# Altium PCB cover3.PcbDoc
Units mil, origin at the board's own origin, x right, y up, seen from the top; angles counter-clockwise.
Board outline 7500 x 2300 mil, 2 copper layers (Top Layer, Bottom Layer); 34 components, 23 nets, 169 pads, 36 vias.
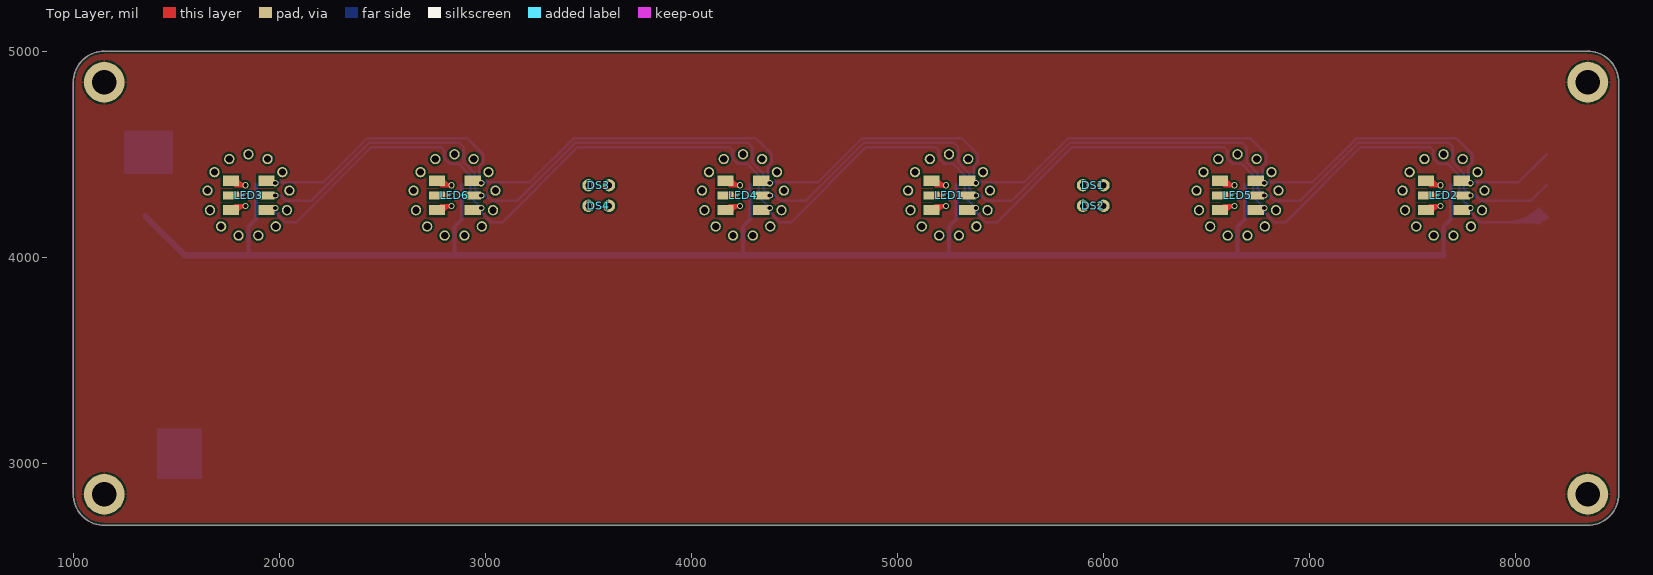
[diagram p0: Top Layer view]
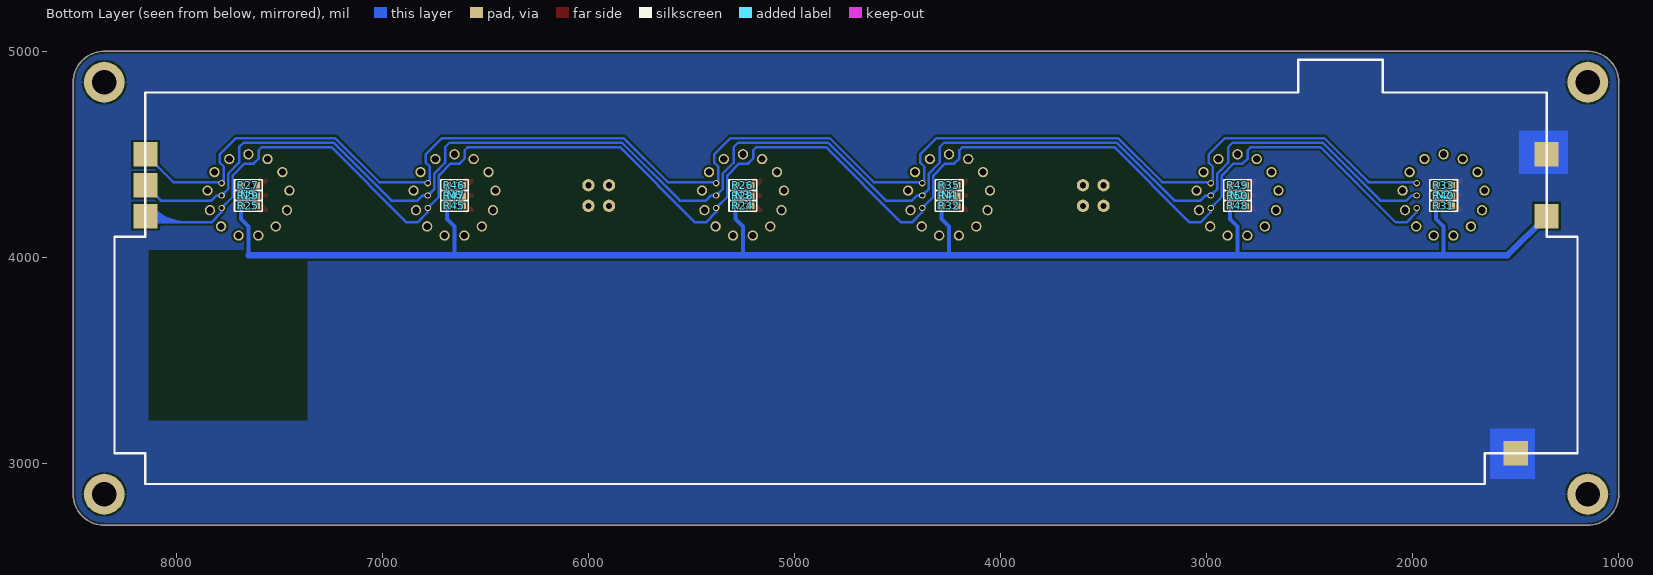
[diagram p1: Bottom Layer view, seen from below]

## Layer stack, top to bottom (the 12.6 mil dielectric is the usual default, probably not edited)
Top Solder: solder mask 0.4, Solder Resist, Dk 3.5
Top Layer: signal copper 1.4
Dielectric 1: dielectric 12.6, FR-4, Dk 4.8
Bottom Layer: signal copper 1.4
Bottom Solder: solder mask 0.4, Solder Resist, Dk 3.5

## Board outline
1150,2700 cw(c1150,2850) 1000,2850 1000,4850 cw(c1150,4850) 1150,5000 8350,5000 cw(c8350,4850) 8500,4850 8500,2850 cw(c8350,2850) 8350,2700

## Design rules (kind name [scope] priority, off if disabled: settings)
Clearance [All] p1: gap=10
PolygonConnect [All] p1: connectstyle=Relief reliefconductorwidth=10 reliefentries=4 polygonreliefangle="90 Angle" airgapwidth=10
RoutingVias [All] p1: holewidth=28 width=50 viastyle="Through Hole" minholewidth=28 minwidth=50 maxholewidth=28 maxwidth=50
SolderMaskExpansion [All] p1: expansion=4
Width [All] p1: maxlimit=10 minlimit=10 preferedwidth=10
29 further rules are at their usual default settings.

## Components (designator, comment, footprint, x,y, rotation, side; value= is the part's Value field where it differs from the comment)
DS1 "Lamp Neon" LED_PIN2 5900,4350 r0 top
DS2 "Lamp Neon" LED_PIN2 5900,4250 r0 top
DS3 "Lamp Neon" LED_PIN2 3600,4350 r180 top
DS4 "Lamp Neon" LED_PIN2 3600,4250 r180 top
LED1 "LED_RGB_5050" LED_RGB_5050 5165,4230 r90 top
LED2 "LED_RGB_5050" LED_RGB_5050 7565,4230 r90 top
LED3 "LED_RGB_5050" LED_RGB_5050 1765,4230 r90 top
LED4 "LED_RGB_5050" LED_RGB_5050 4165,4230 r90 top
LED5 "LED_RGB_5050" LED_RGB_5050 6565,4230 r90 top
LED6 "LED_RGB_5050" LED_RGB_5050 2765,4230 r90 top
N1 "ИН-14" IN14 2850,4300 r0 bottom
N2 "ИН-14" IN14 1850,4300 r0 bottom
N3 "ИН-14" IN14 5250,4300 r0 bottom
N4 "ИН-14" IN14 4250,4300 r0 bottom
N5 "ИН-14" IN14 7650,4300 r0 bottom
N6 "ИН-14" IN14 6650,4300 r0 bottom
R24 "Res2" "R 0603" 5250,4250 r0 bottom
R25 "Res2" "R 0603" 7650,4250 r0 bottom
R26 "Res2" "R 0603" 5250,4350 r0 bottom
R27 "Res2" "R 0603" 7650,4350 r0 bottom
R28 "Res2" "R 0603" 5250,4300 r0 bottom
R29 "Res2" "R 0603" 7650,4300 r0 bottom
R31 "Res2" "R 0603" 1850,4250 r0 bottom
R32 "Res2" "R 0603" 4250,4250 r0 bottom
R33 "Res2" "R 0603" 1850,4350 r0 bottom
R35 "Res2" "R 0603" 4250,4350 r0 bottom
R40 "Res2" "R 0603" 1850,4300 r0 bottom
R41 "Res2" "R 0603" 4250,4300 r0 bottom
R45 "Res2" "R 0603" 6650,4250 r0 bottom
R46 "Res2" "R 0603" 6650,4350 r0 bottom
R47 "Res2" "R 0603" 6650,4300 r0 bottom
R48 "Res2" "R 0603" 2850,4250 r0 bottom
R49 "Res2" "R 0603" 2850,4350 r0 bottom
R50 "Res2" "R 0603" 2850,4300 r0 bottom

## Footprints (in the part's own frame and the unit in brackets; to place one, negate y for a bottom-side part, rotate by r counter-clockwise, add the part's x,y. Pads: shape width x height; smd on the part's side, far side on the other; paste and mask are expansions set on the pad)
IN14 [mil]
  round 50 hole 35: 1(0,-200) 2(-93.03,-177.05) 3(-164.65,-113.54) 4(-198.55,-24.03) 5(-186.98,70.99) 6(-132.58,149.74) 7(-47.81,194.2) 8(47.91,194.18) 9(132.65,149.68) 10(187.01,70.89) 11(198.54,-24.13) 12(164.59,-113.63) 13(92.94,-177.09)
LED_PIN2 [mil] "Photosensitive Diode; 2 Leads"
  round 60 hole 30: 1(0,0) 2(100,0)
LED_RGB_5050 [mm]
  rect 1.27x2 smd: 0(0,0) 1(3.6,0) 3(0,-4.4) 4(3.6,-4.4)
  rect 1x2 smd: 2(1.778,0) 5(1.778,-4.4)
"R 0603" [mil] "1/10W贴片电阻"
  rect 40x31.5 smd: 1(-36.5,0) 2(36.5,0)
  silkscreen extent -68,-26 68,26, body extent -31,-16 31,16, height 16

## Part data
DS1 DS2 DS3 DS4: "Neon Lamp"
R24 R25 R26 R27 R28 R29 R31 R32 R33 R35 R40 R41 R45 R46 R47 R48 R49 R50: "Resistor"

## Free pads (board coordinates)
  round 196.85 hole 118.11: 0(1150,2850) 0(1150,4850) 0(8350,2850) 0(8350,4850)
  rect 118.11x118.11 smd far side: 0(8150,4500) 1(8150,4350) 2(8150,4200) 3(1350,4500) 4(1350,4200) 5(1500,3050)
  rect 118.11x118.11 on Bottom Solder: 5(1500,3050)

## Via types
v1: diameter 30, hole 20, Top Layer to Bottom Layer, 36 vias

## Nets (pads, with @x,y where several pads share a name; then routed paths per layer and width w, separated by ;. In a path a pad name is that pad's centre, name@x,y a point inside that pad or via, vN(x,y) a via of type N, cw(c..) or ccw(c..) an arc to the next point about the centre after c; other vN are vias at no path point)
5V: pad.4 R24.2 R25.2 R26.2 R27.2 R28.2 R29.2 R31.2 R32.2 R33.2 R35.2 R40.2 R41.2 R45.2 R46.2 R47.2 R48.2 R49.2 R50.2 | length 8509.4
  Bottom Layer w20: 1850,4010 1850,4150 1886.5,4186.5 R31.2 R40.2 R33.2 ; 2850,4010 2850,4150 2886.5,4186.5 R48.2 R50.2 R49.2 ; 4250,4010 4250,4150 4286.5,4186.5 R32.2 R41.2 R35.2 ; 5250,4010 5250,4150 5286.5,4186.5 R24.2 R28.2 R26.2 ; 6650,4010 6650,4150 6686.5,4186.5 R45.2 R47.2 R46.2 ; 7650,4010 7650,4150 7686.5,4186.5 R25.2 R29.2 R27.2
  Bottom Layer w30: pad.4 1540,4010 7650,4010
GND: pad.0@1150,2850 pad.0@1150,4850 pad.0@8350,2850 pad.0@8350,4850 pad.3 pad.5@1500,3050
LED_B: LED1.3 LED2.3 LED3.3 LED4.3 LED5.3 LED6.3 pad.2 | length 10835.3
  Bottom Layer w12: v1(1980,4240) 1980,4220 ; v1@2971,4240.07 ccw(c2949.85,4240.24) 2964.63,4255.37 ; v1@2971,4240.1 ccw(c2950.14,4240.35) 2965.06,4254.93 ccw(c2979.65,4269.86) v1@2979.9,4249 ; v1@2979.93,4249 cw(c2979.76,4270.15) 2964.63,4255.37 ; v1@4371,4240.07 ccw(c4349.85,4240.24) 4364.63,4255.37 ; v1@4371,4240.1 ccw(c4350.14,4240.35) 4365.06,4254.93 ccw(c4379.65,4269.86) v1@4379.9,4249 ; v1@4379.93,4249 cw(c4379.76,4270.15) 4364.63,4255.37 ; v1@5371,4240.07 ccw(c5349.85,4240.24) 5364.63,4255.37 ; v1@5371,4240.1 ccw(c5350.14,4240.35) 5365.06,4254.93 ccw(c5379.65,4269.86) v1@5379.9,4249 ; v1@5379.93,4249 cw(c5379.76,4270.15) 5364.63,4255.37 ; v1@6771,4240.07 ccw(c6749.85,4240.24) 6764.63,4255.37 ; v1@6771,4240.1 ccw(c6750.14,4240.35) 6765.06,4254.93 ccw(c6779.65,4269.86) v1@6779.9,4249 ; v1@6779.93,4249 cw(c6779.76,4270.15) 6764.63,4255.37 ; v1@7771,4240.07 ccw(c7749.85,4240.24) 7764.63,4255.37 ; v1@7771,4240.1 ccw(c7750.14,4240.35) 7765.06,4254.93 ccw(c7779.65,4269.86) v1@7779.9,4249 ; v1@7779.93,4249 cw(c7779.76,4270.15) 7764.63,4255.37 ; 8081.81,4179.65 ccw(c8066.43,4206.28) pad.2@8097.09,4203.98 ; 8083.99,4193.36 ccw(c8067.63,4220.72) pad.2@8098.55,4212.94 ; pad.2 8120,4170 7830,4170 7780,4220 ; 1980,4220 ccw(c1962.28,4220) 1974.03,4233.26 cw(c1962.28,4220) 1980,4220 ; 1980,4220 cw(c1997.72,4220) 1985.97,4233.26 ccw(c1997.72,4220) 1980,4220 ; 1980,4220 2030,4170 2082.23,4170 2447.23,4535 2785,4535 2800,4520 2800,4480 2825,4455 2868.89,4455 2926,4397.89 2926,4294 v1(2980,4240) 2980,4220 ; 2964.64,4255.36 ccw(c2980,4270.73) 2980,4249 cw(c2980,4270.73) 2964.64,4255.36 ; 2964.64,4255.36 cw(c2949.27,4240) 2971,4240 ccw(c2949.27,4240) 2964.64,4255.36 ; 2980,4220 ccw(c2962.28,4220) 2974.03,4233.26 cw(c2962.28,4220) 2980,4220 ; 2980,4220 cw(c2997.72,4220) 2985.97,4233.26 ccw(c2997.72,4220) 2980,4220 ; 2980,4220 3030,4170 3082.23,4170 3447.23,4535 4185,4535 4200,4520 4200,4480 4225,4455 4268.89,4455 4326,4397.89 4326,4294 v1(4380,4240) 4380,4220 ; 4364.64,4255.36 ccw(c4380,4270.73) 4380,4249 cw(c4380,4270.73) 4364.64,4255.36 ; 4364.64,4255.36 cw(c4349.27,4240) 4371,4240 ccw(c4349.27,4240) 4364.64,4255.36 ; 4380,4220 ccw(c4362.28,4220) 4374.03,4233.26 cw(c4362.28,4220) 4380,4220 ; 4380,4220 cw(c4397.72,4220) 4385.97,4233.26 ccw(c4397.72,4220) 4380,4220 ; 4380,4220 4430,4170 4482.23,4170 4847.23,4535 5185,4535 5200,4520 5200,4480 5225,4455 5268.89,4455 5326,4397.89 5326,4294 v1(5380,4240) 5380,4220 ; 5364.64,4255.36 ccw(c5380,4270.73) 5380,4249 cw(c5380,4270.73) 5364.64,4255.36 ; 5364.64,4255.36 cw(c5349.27,4240) 5371,4240 ccw(c5349.27,4240) 5364.64,4255.36 ; 5380,4220 ccw(c5362.28,4220) 5374.03,4233.26 cw(c5362.28,4220) 5380,4220 ; 5380,4220 cw(c5397.72,4220) 5385.97,4233.26 ccw(c5397.72,4220) 5380,4220 ; 5380,4220 5430,4170 5482.23,4170 5847.23,4535 6585,4535 6600,4520 6600,4480 6625,4455 6668.89,4455 6726,4397.89 6726,4294 v1(6780,4240) 6780,4220 ; 6764.64,4255.36 ccw(c6780,4270.73) 6780,4249 cw(c6780,4270.73) 6764.64,4255.36 ; 6764.64,4255.36 cw(c6749.27,4240) 6771,4240 ccw(c6749.27,4240) 6764.64,4255.36 ; 6780,4220 ccw(c6762.28,4220) 6774.03,4233.26 cw(c6762.28,4220) 6780,4220 ; 6780,4220 cw(c6797.72,4220) 6785.97,4233.26 ccw(c6797.72,4220) 6780,4220 ; 6780,4220 6830,4170 6882.23,4170 7247.23,4535 7585,4535 7600,4520 7600,4480 7625,4455 7668.89,4455 7726,4397.89 7726,4294 v1(7780,4240) 7780,4220 ; 7764.64,4255.36 ccw(c7780,4270.73) 7780,4249 cw(c7780,4270.73) 7764.64,4255.36 ; 7764.64,4255.36 cw(c7749.27,4240) 7771,4240 ccw(c7749.27,4240) 7764.64,4255.36 ; 7780,4220 ccw(c7762.28,4220) 7774.03,4233.26 cw(c7762.28,4220) 7780,4220 ; 7780,4220 cw(c7797.72,4220) 7785.97,4233.26 ccw(c7797.72,4220) 7780,4220 ; pad.2@8094.34,4170 ccw(c8094.34,4255.66) 8154.91,4195.09 cw(c8094.34,4255.66) pad.2@8094.34,4170 ; pad.2@8094.34,4170 cw(c8094.34,4144.34) 8112.48,4162.48 ccw(c8094.34,4144.34) pad.2@8094.34,4170 ; 7949.49,4170 ccw(c7949.49,4400.51) 8112.48,4237.52 cw(c7949.49,4400.51) 7949.49,4170 ; 7978.46,4170 ccw(c7978.46,4371.54) 8120.97,4229.03 cw(c7978.46,4371.54) 7978.46,4170 ; 8007.43,4170 ccw(c8007.43,4342.57) 8129.45,4220.55 cw(c8007.43,4342.57) 8007.43,4170 ; 8036.4,4170 ccw(c8036.4,4313.6) 8137.94,4212.06 cw(c8036.4,4313.6) 8036.4,4170 ; 8065.37,4170 ccw(c8065.37,4284.63) 8146.43,4203.57 cw(c8065.37,4284.63) 8065.37,4170
LED_G: LED1.4 LED2.4 LED3.4 LED4.4 LED5.4 LED6.4 pad.0@8150,4500 | length 7635.5
  Bottom Layer w12: v1@1985.13,4365.13 2215.13,4365.13 2429,4579 2911,4579 2990,4500 2990,4460 2970,4440 2970,4370 v1(2980,4360) 2985.13,4365.13 3215.13,4365.13 3429,4579 4311,4579 4390,4500 4390,4460 4370,4440 4370,4370 v1(4380,4360) ; v1@4385.13,4365.13 4615.13,4365.13 4829,4579 5311,4579 5390,4500 5390,4460 5370,4440 5370,4370 v1(5380,4360) 5385.13,4365.13 5615.13,4365.13 5829,4579 6711,4579 6790,4500 6790,4460 6770,4440 6770,4370 v1(6780,4360) ; v1@6785.13,4365.13 7015.13,4365.13 7229,4579 7711,4579 7790,4500 7790,4460 7770,4440 7770,4370 v1(7780,4360) 7785.13,4365.13 8015.13,4365.13 pad.0@8150,4500
  other v1: 1980,4360
LED_R: LED1.5 LED2.5 LED3.5 LED4.5 LED5.5 LED6.5 pad.1 | length 8903.8
  Bottom Layer w12: v1(1980,4300) 2005,4300 2030,4275 2156.11,4275 2438.11,4557 2873,4557 2895,4535 2895,4460 2948,4407 2948,4332 v1(2980,4300) 3005,4300 3030,4275 3156.11,4275 3438.11,4557 4273,4557 4295,4535 4295,4460 4348,4407 4348,4332 v1(4380,4300) 4405,4300 4430,4275 4556.11,4275 4838.11,4557 5273,4557 5295,4535 5295,4460 5348,4407 5348,4332 v1(5380,4300) 5405,4300 5430,4275 5556.11,4275 5838.11,4557 6673,4557 6695,4535 6695,4460 6748,4407 6748,4332 v1(6780,4300) 6805,4300 6830,4275 6956.11,4275 7238.11,4557 7673,4557 7695,4535 7695,4460 7748,4407 7748,4332 v1(7780,4300) 7805,4300 7830,4275 8075,4275 pad.1 ; v1@2971,4300.07 ccw(c2949.85,4300.24) 2964.63,4315.37 ; v1@2971,4300.1 ccw(c2950.14,4300.35) 2965.06,4314.93 ccw(c2979.65,4329.86) v1@2979.9,4309 ; v1@2979.93,4309 cw(c2979.76,4330.15) 2964.63,4315.37 ; v1@4371,4300.07 ccw(c4349.85,4300.24) 4364.63,4315.37 ; v1@4371,4300.1 ccw(c4350.14,4300.35) 4365.06,4314.93 ccw(c4379.65,4329.86) v1@4379.9,4309 ; v1@4379.93,4309 cw(c4379.76,4330.15) 4364.63,4315.37 ; v1@5371,4300.07 ccw(c5349.85,4300.24) 5364.63,4315.37 ; v1@5371,4300.1 ccw(c5350.14,4300.35) 5365.06,4314.93 ccw(c5379.65,4329.86) v1@5379.9,4309 ; v1@5379.93,4309 cw(c5379.76,4330.15) 5364.63,4315.37 ; v1@6771,4300.07 ccw(c6749.85,4300.24) 6764.63,4315.37 ; v1@6771,4300.1 ccw(c6750.14,4300.35) 6765.06,4314.93 ccw(c6779.65,4329.86) v1@6779.9,4309 ; v1@6779.93,4309 cw(c6779.76,4330.15) 6764.63,4315.37 ; v1@7771,4300.07 ccw(c7749.85,4300.24) 7764.63,4315.37 ; v1@7771,4300.1 ccw(c7750.14,4300.35) 7765.06,4314.93 ccw(c7779.65,4329.86) v1@7779.9,4309 ; v1@7779.93,4309 cw(c7779.76,4330.15) 7764.63,4315.37 ; 2001.73,4300 ccw(c2001.73,4278.27) 1986.36,4293.64 cw(c2001.73,4278.27) 2001.73,4300 ; 2001.73,4300 cw(c2001.73,4321.73) 1986.36,4306.36 ccw(c2001.73,4321.73) 2001.73,4300 ; 2964.64,4315.36 ccw(c2980,4330.73) 2980,4309 cw(c2980,4330.73) 2964.64,4315.36 ; 2964.64,4315.36 cw(c2949.27,4300) 2971,4300 ccw(c2949.27,4300) 2964.64,4315.36 ; 3001.73,4300 ccw(c3001.73,4278.27) 2986.36,4293.64 cw(c3001.73,4278.27) 3001.73,4300 ; 3001.73,4300 cw(c3001.73,4321.73) 2986.36,4306.36 ccw(c3001.73,4321.73) 3001.73,4300 ; 4364.64,4315.36 ccw(c4380,4330.73) 4380,4309 cw(c4380,4330.73) 4364.64,4315.36 ; 4364.64,4315.36 cw(c4349.27,4300) 4371,4300 ccw(c4349.27,4300) 4364.64,4315.36 ; 4401.73,4300 ccw(c4401.73,4278.27) 4386.36,4293.64 cw(c4401.73,4278.27) 4401.73,4300 ; 4401.73,4300 cw(c4401.73,4321.73) 4386.36,4306.36 ccw(c4401.73,4321.73) 4401.73,4300 ; 5364.64,4315.36 ccw(c5380,4330.73) 5380,4309 cw(c5380,4330.73) 5364.64,4315.36 ; 5364.64,4315.36 cw(c5349.27,4300) 5371,4300 ccw(c5349.27,4300) 5364.64,4315.36 ; 5401.73,4300 ccw(c5401.73,4278.27) 5386.36,4293.64 cw(c5401.73,4278.27) 5401.73,4300 ; 5401.73,4300 cw(c5401.73,4321.73) 5386.36,4306.36 ccw(c5401.73,4321.73) 5401.73,4300 ; 6764.64,4315.36 ccw(c6780,4330.73) 6780,4309 cw(c6780,4330.73) 6764.64,4315.36 ; 6764.64,4315.36 cw(c6749.27,4300) 6771,4300 ccw(c6749.27,4300) 6764.64,4315.36 ; 6801.73,4300 ccw(c6801.73,4278.27) 6786.36,4293.64 cw(c6801.73,4278.27) 6801.73,4300 ; 6801.73,4300 cw(c6801.73,4321.73) 6786.36,4306.36 ccw(c6801.73,4321.73) 6801.73,4300 ; 7764.64,4315.36 ccw(c7780,4330.73) 7780,4309 cw(c7780,4330.73) 7764.64,4315.36 ; 7764.64,4315.36 cw(c7749.27,4300) 7771,4300 ccw(c7749.27,4300) 7764.64,4315.36 ; 7801.73,4300 ccw(c7801.73,4278.27) 7786.36,4293.64 cw(c7801.73,4278.27) 7801.73,4300 ; 7801.73,4300 cw(c7801.73,4321.73) 7786.36,4306.36 ccw(c7801.73,4321.73) 7801.73,4300
NetLED1_0: LED1.0 R24.1 | length 277.5
  Top Layer w20: LED1.0 5185,4250 v1(5235,4250) ; LED1.0@5188.84,4241.64 ccw(c5198.49,4253.49) 5210.09,4243.54 ; v1(5235,4250) ccw(c5235,4203.29) 5192.89,4223.51 cw(c5235,4203.29) v1(5235,4250) ; LED1.0@5174.86,4232.16 cw(c5203.21,4218.55) 5203.21,4250 ccw(c5203.21,4218.55) LED1.0@5174.86,4232.16
NetLED1_1: LED1.1 R26.1 | length 285.5
  Top Layer w20: LED1.1 5186.73,4350 v1(5235,4350) ; LED1.1@5188.04,4359.49 cw(c5197.3,4346.43) 5209.89,4356.31 ; v1(5235,4350) cw(c5235,4395.49) 5193.16,4377.62 ccw(c5235,4395.49) v1(5235,4350) ; LED1.1@5174.77,4369.77 ccw(c5204.71,4382.55) 5204.71,4350 cw(c5204.71,4382.55) LED1.1@5174.77,4369.77
NetLED1_2: LED1.2 R28.1 | length 143.5
  Top Layer w20: LED1.2 v1(5235,4300) ; 5208.07,4300 ccw(c5208.07,4276.62) 5191.53,4293.15 cw(c5208.07,4276.62) 5208.07,4300 ; 5208.07,4300 cw(c5208.07,4323.38) 5191.53,4306.85 ccw(c5208.07,4323.38) 5208.07,4300
NetLED2_0: LED2.0 R25.1 | length 277.5
  Top Layer w20: LED2.0 7585,4250 v1(7635,4250) ; LED2.0@7588.84,4241.64 ccw(c7598.49,4253.49) 7610.09,4243.54 ; v1(7635,4250) ccw(c7635,4203.29) 7592.89,4223.51 cw(c7635,4203.29) v1(7635,4250) ; LED2.0@7574.86,4232.16 cw(c7603.21,4218.55) 7603.21,4250 ccw(c7603.21,4218.55) LED2.0@7574.86,4232.16
NetLED2_1: LED2.1 R27.1 | length 285.5
  Top Layer w20: LED2.1 7586.73,4350 v1(7635,4350) ; LED2.1@7588.04,4359.49 cw(c7597.3,4346.43) 7609.89,4356.31 ; v1(7635,4350) cw(c7635,4395.49) 7593.16,4377.62 ccw(c7635,4395.49) v1(7635,4350) ; LED2.1@7574.77,4369.77 ccw(c7604.71,4382.55) 7604.71,4350 cw(c7604.71,4382.55) LED2.1@7574.77,4369.77
NetLED2_2: LED2.2 R29.1 | length 143.5
  Top Layer w20: LED2.2 v1(7635,4300) ; 7608.07,4300 ccw(c7608.07,4276.62) 7591.53,4293.15 cw(c7608.07,4276.62) 7608.07,4300 ; 7608.07,4300 cw(c7608.07,4323.38) 7591.53,4306.85 ccw(c7608.07,4323.38) 7608.07,4300
NetLED3_0: LED3.0 R31.1 | length 277.5
  Top Layer w20: LED3.0 1785,4250 v1(1835,4250) ; LED3.0@1788.84,4241.64 ccw(c1798.49,4253.49) 1810.09,4243.54 ; v1(1835,4250) ccw(c1835,4203.29) 1792.89,4223.51 cw(c1835,4203.29) v1(1835,4250) ; LED3.0@1774.86,4232.16 cw(c1803.21,4218.55) 1803.21,4250 ccw(c1803.21,4218.55) LED3.0@1774.86,4232.16
NetLED3_1: LED3.1 R33.1 | length 285.5
  Top Layer w20: LED3.1 1786.73,4350 v1(1835,4350) ; LED3.1@1788.04,4359.49 cw(c1797.3,4346.43) 1809.89,4356.31 ; v1(1835,4350) cw(c1835,4395.49) 1793.16,4377.62 ccw(c1835,4395.49) v1(1835,4350) ; LED3.1@1774.77,4369.77 ccw(c1804.71,4382.55) 1804.71,4350 cw(c1804.71,4382.55) LED3.1@1774.77,4369.77
NetLED3_2: LED3.2 R40.1 | length 143.5
  Top Layer w20: LED3.2 v1(1835,4300) ; 1808.07,4300 ccw(c1808.07,4276.62) 1791.53,4293.15 cw(c1808.07,4276.62) 1808.07,4300 ; 1808.07,4300 cw(c1808.07,4323.38) 1791.53,4306.85 ccw(c1808.07,4323.38) 1808.07,4300
NetLED4_0: LED4.0 R32.1 | length 277.5
  Top Layer w20: LED4.0 4185,4250 v1(4235,4250) ; LED4.0@4188.84,4241.64 ccw(c4198.49,4253.49) 4210.09,4243.54 ; v1(4235,4250) ccw(c4235,4203.29) 4192.89,4223.51 cw(c4235,4203.29) v1(4235,4250) ; LED4.0@4174.86,4232.16 cw(c4203.21,4218.55) 4203.21,4250 ccw(c4203.21,4218.55) LED4.0@4174.86,4232.16
NetLED4_1: LED4.1 R35.1 | length 285.5
  Top Layer w20: LED4.1 4186.73,4350 v1(4235,4350) ; LED4.1@4188.04,4359.49 cw(c4197.3,4346.43) 4209.89,4356.31 ; v1(4235,4350) cw(c4235,4395.49) 4193.16,4377.62 ccw(c4235,4395.49) v1(4235,4350) ; LED4.1@4174.77,4369.77 ccw(c4204.71,4382.55) 4204.71,4350 cw(c4204.71,4382.55) LED4.1@4174.77,4369.77
NetLED4_2: LED4.2 R41.1 | length 143.5
  Top Layer w20: LED4.2 v1(4235,4300) ; 4208.07,4300 ccw(c4208.07,4276.62) 4191.53,4293.15 cw(c4208.07,4276.62) 4208.07,4300 ; 4208.07,4300 cw(c4208.07,4323.38) 4191.53,4306.85 ccw(c4208.07,4323.38) 4208.07,4300
NetLED5_0: LED5.0 R45.1 | length 277.5
  Top Layer w20: LED5.0 6585,4250 v1(6635,4250) ; LED5.0@6588.84,4241.64 ccw(c6598.49,4253.49) 6610.09,4243.54 ; v1(6635,4250) ccw(c6635,4203.29) 6592.89,4223.51 cw(c6635,4203.29) v1(6635,4250) ; LED5.0@6574.86,4232.16 cw(c6603.21,4218.55) 6603.21,4250 ccw(c6603.21,4218.55) LED5.0@6574.86,4232.16
NetLED5_1: LED5.1 R46.1 | length 285.5
  Top Layer w20: LED5.1 6586.73,4350 v1(6635,4350) ; LED5.1@6588.04,4359.49 cw(c6597.3,4346.43) 6609.89,4356.31 ; v1(6635,4350) cw(c6635,4395.49) 6593.16,4377.62 ccw(c6635,4395.49) v1(6635,4350) ; LED5.1@6574.77,4369.77 ccw(c6604.71,4382.55) 6604.71,4350 cw(c6604.71,4382.55) LED5.1@6574.77,4369.77
NetLED5_2: LED5.2 R47.1 | length 143.5
  Top Layer w20: LED5.2 v1(6635,4300) ; 6608.07,4300 ccw(c6608.07,4276.62) 6591.53,4293.15 cw(c6608.07,4276.62) 6608.07,4300 ; 6608.07,4300 cw(c6608.07,4323.38) 6591.53,4306.85 ccw(c6608.07,4323.38) 6608.07,4300
NetLED6_0: LED6.0 R48.1 | length 277.5
  Top Layer w20: LED6.0 2785,4250 v1(2835,4250) ; LED6.0@2788.84,4241.64 ccw(c2798.49,4253.49) 2810.09,4243.54 ; v1(2835,4250) ccw(c2835,4203.29) 2792.89,4223.51 cw(c2835,4203.29) v1(2835,4250) ; LED6.0@2774.86,4232.16 cw(c2803.21,4218.55) 2803.21,4250 ccw(c2803.21,4218.55) LED6.0@2774.86,4232.16
NetLED6_1: LED6.1 R49.1 | length 285.5
  Top Layer w20: LED6.1 2786.73,4350 v1(2835,4350) ; LED6.1@2788.04,4359.49 cw(c2797.3,4346.43) 2809.89,4356.31 ; v1(2835,4350) cw(c2835,4395.49) 2793.16,4377.62 ccw(c2835,4395.49) v1(2835,4350) ; LED6.1@2774.77,4369.77 ccw(c2804.71,4382.55) 2804.71,4350 cw(c2804.71,4382.55) LED6.1@2774.77,4369.77
NetLED6_2: LED6.2 R50.1 | length 143.5
  Top Layer w20: LED6.2 v1(2835,4300) ; 2808.07,4300 ccw(c2808.07,4276.62) 2791.53,4293.15 cw(c2808.07,4276.62) 2808.07,4300 ; 2808.07,4300 cw(c2808.07,4323.38) 2791.53,4306.85 ccw(c2808.07,4323.38) 2808.07,4300
pads on no net: DS1.1 DS1.2 DS2.1 DS2.2 DS3.1 DS3.2 DS4.1 DS4.2 N1.1 N1.2 N1.3 N1.4 N1.5 N1.6 N1.7 N1.8 N1.9 N1.10 N1.11 N1.12 N1.13 N2.1 N2.2 N2.3 N2.4 N2.5 N2.6 N2.7 N2.8 N2.9 N2.10 N2.11 N2.12 N2.13 N3.1 N3.2 N3.3 N3.4 N3.5 N3.6 N3.7 N3.8 N3.9 N3.10 N3.11 N3.12 N3.13 N4.1 N4.2 N4.3 N4.4 N4.5 N4.6 N4.7 N4.8 N4.9 N4.10 N4.11 N4.12 N4.13 N5.1 N5.2 N5.3 N5.4 N5.5 N5.6 N5.7 N5.8 N5.9 N5.10 N5.11 N5.12 N5.13 N6.1 N6.2 N6.3 N6.4 N6.5 N6.6 N6.7 N6.8 N6.9 N6.10 N6.11 N6.12 N6.13

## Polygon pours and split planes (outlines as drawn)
GND on Bottom Layer "Top Layer-No Net" (solid, remove dead copper, pour order 2): 875,5115 795,5035 795,2490 8620,2490 8860,2730 8795,2795 8795,5120
GND on Top Layer "Top Layer-No Net" (solid, remove dead copper, pour order 4): 805,5460 805,2430 910,2325 1150,2565 8895,2565 8895,4915 8580,5230

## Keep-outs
Keep-Out Layer:
  lines w5: 1000,2850 ccw(c1150,2850) 1150,2700 2550,2700 8350,2700 ccw(c8350,2850) 8500,2850 8500,4850 ccw(c8350,4850) 8350,5000 1150,5000 ccw(c1150,4850) 1000,4850 1000,2850

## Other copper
Bottom Layer:
  rectangle net GND: 1245,4405 1485,4615
  rectangle net GND: 1405,2925 1625,3170
  pour cut-out: 8135,4035 8135,3210 7365,3210 7365,4035

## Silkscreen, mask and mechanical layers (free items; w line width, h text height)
Bottom Overlay:
  lines w11.81: 8150,4250 8150,4650 ; 8150,4650 8150,4800 2555,4800 2555,4960 2145,4960 2145,4800 1350,4800 1350,4100 1200,4100 1200,3050 1650,3050 1650,2900 8150,2900 8150,3050 8300,3050 8300,4100 8150,4100 8150,4650
Top Solder:
  drawing of 97974 lines, arcs and shapes, not listed
  text "Nixie Tube" at 4490,3825 h150
  text "Getter" at 1590,3810 h60
  text "Neon" at 1655,3720 h60
  text "A Nixie tube, or cold cathode display, is an electronic device for displaying numerals or other information using glow discharge. The glass" at 2490,3700 h100
  text "Cathode Segments" at 1885,3600 h60
  text "tube contains a wire-mesh anode and multiple cathodes, shaped like numerals or other symbols. Applying power to one cathode surrounds it with" at 2390,3600 h100
  text "an orange glow discharge. Tube is filled with a gas at low pressure, usually mostly neon and often a little mercury or argon, in a Penning mixture." at 2390,3500 h100
  text "Although it resembles a vacuum tube in appearance, its operation does not depend on thermionic emission of electrons from a heated cathode." at 2490,3400 h100
  text "It is therefore called a cold-cathode tube (a form of gas-filled tube), or a variant of neon lamp. Such tubes rarely exceed 40℃ even under the most" at 2390,3300 h100
  text "severe of operating conditions in a room at ambient temperature. Vacuum fluorescent displays from the same era use completely different technology" at 2390,3200 h100
  text "Glass" at 1680,3190 h60
  text "Pins" at 1645,3110 h60
  text "—they have a heated cathode together with a control grid and shaped phosphor anodes; Nixies have no heater or control grid, typically a single" at 2390,3100 h100
  text "Anode Grid" at 1730,3025 h60
  text "anode, and shaped bare metal cathodes." at 2410,3000 h100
